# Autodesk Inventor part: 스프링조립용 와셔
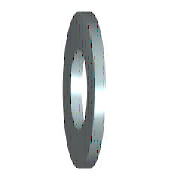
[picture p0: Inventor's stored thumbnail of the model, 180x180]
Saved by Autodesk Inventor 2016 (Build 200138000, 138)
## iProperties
IsCustomPart: 1
Created: 2012-02
Part Number: 스프링조립용 와셔
Material: 강철, 연강
Description: 평면 와셔
Document SubType Name: Modeling
Standard: KS B 1326
Designer: mduedu
Standards Organization: KS
Language: ko-KR
Size Designation: 12x24
Categories: <MemberInstance><Categories><Category DisplayName="조임쇠" InternalName="e4da775c-781d-43d5-af7c-5136215cf5a6" Mnemonic="FSTN"><Category DisplayName="와셔" InternalN
Density: 7.85 g/cm^3
Appearance: 강철
Mass: 5.38854 g
Surface Area: 8.71478 cm^2
Volume: 0.686438 cm^3
Author: mduedu
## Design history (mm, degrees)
sketch "스케치"
  geometry: C1 r 12 at (0, 0); C2 r 7 at (0, 0); 1 further point
  constraints: 2 centre point, 2 coincident
  dimensions: "d0" = 14 diameter of C2 (= SD1); "d1" = 24 diameter of C1 (= SD2)
extrude "본체" new body sketch "스케치" distance "d2" = 2.3 (= SD); taper "d3" = 0 deg
workaxis "Work Axis1"
workplane "Work Plane1"
body "Solid1"
other parameters: "SD1" = 14 [user parameter; used in 1 equation term], "SD2" = 24 [user parameter; used in 1 equation term], "SD" = 2.3 [user parameter; used in 1 equation term], "d4" = 0, "d5" = 0, "d6" = 0, "d7" = 0, "NND" = 12 [user parameter]
